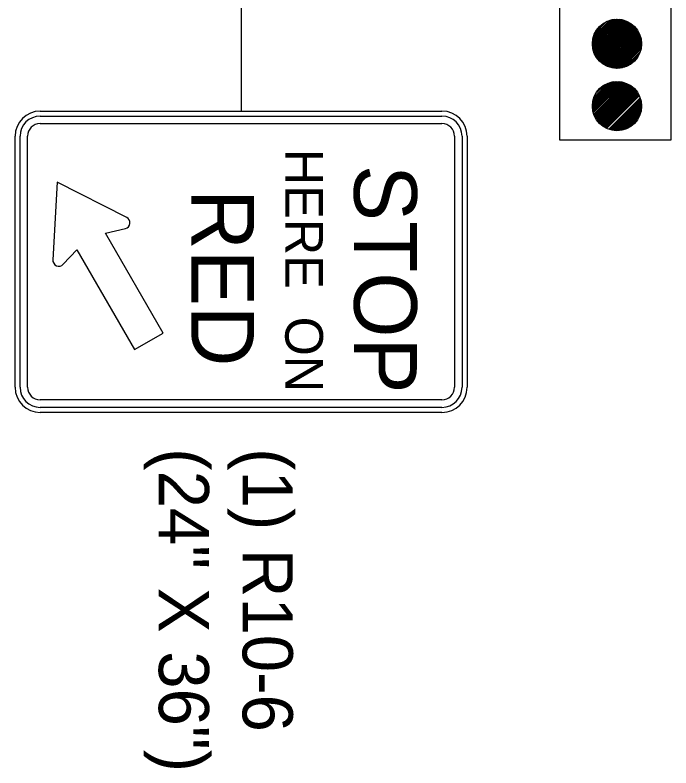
# Model space of a CAD drawing. Extents: x 1926586 to 1930787, y 596452 to 599566.
# Drawn here: x 1928552.1 to 1928630.5, y 597303.5 to 597393.4 of the extents above; entities that cross this region are included whole.
import ezdxf

# ---------------------------------------------------------------- set-up
doc = ezdxf.new("R2010")
doc.units = 0
for name, color, linetype in [('Default', 7, 'Continuous'), ('P_TC_Signs_Permanent', 7, 'Continuous'), ('R_Border', 7, 'Continuous')]:
    doc.layers.add(name, color=color, linetype=linetype)

msp = doc.modelspace()

# ---------------------------------------------------------------- linework, layer by layer
at = {"layer": 'Default'}
for p, q in [((1928621.108, 597390.048), (1928624.007, 597392.947)), ((1928621.111, 597389.87), (1928624.185, 597392.944)), ((1928621.117, 597390.238), (1928623.817, 597392.938)), ((1928621.124, 597389.702), (1928624.353, 597392.932)), ((1928621.14, 597390.442), (1928623.613, 597392.915)), ((1928621.145, 597389.542), (1928624.513, 597392.911)), ((1928621.173, 597389.389), (1928624.666, 597392.882)), ((1928621.183, 597390.665), (1928623.39, 597392.872)), ((1928621.208, 597389.244), (1928624.811, 597392.847)), ((1928621.249, 597389.104), (1928624.951, 597392.806)), ((1928621.252, 597390.916), (1928623.14, 597392.803)), ((1928621.296, 597388.97), (1928625.085, 597392.759)), ((1928621.348, 597388.841), (1928625.214, 597392.707)), ((1928621.366, 597391.21), (1928622.845, 597392.689)), ((1928621.405, 597388.717), (1928625.338, 597392.65)), ((1928621.467, 597388.598), (1928625.457, 597392.588)), ((1928621.533, 597388.483), (1928625.572, 597392.522)), ((1928621.582, 597391.608), (1928622.448, 597392.473)), ((1928621.603, 597388.372), (1928625.683, 597392.452)), ((1928621.677, 597388.266), (1928625.789, 597392.378)), ((1928621.756, 597388.164), (1928625.892, 597392.299)), ((1928621.839, 597388.065), (1928625.99, 597392.217)), ((1928621.925, 597387.971), (1928626.084, 597392.13)), ((1928622.016, 597387.88), (1928626.175, 597392.04)), ((1928622.11, 597387.794), (1928626.261, 597391.945)), ((1928622.208, 597387.711), (1928626.344, 597391.847)), ((1928622.311, 597387.633), (1928626.422, 597391.744)), ((1928622.417, 597387.558), (1928626.497, 597391.638)), ((1928622.528, 597387.488), (1928626.567, 597391.527)), ((1928622.643, 597387.422), (1928626.633, 597391.412)), ((1928622.762, 597387.361), (1928626.695, 597391.293)), ((1928622.886, 597387.304), (1928626.751, 597391.169)), ((1928623.015, 597387.252), (1928626.803, 597391.04)), ((1928623.149, 597387.205), (1928626.85, 597390.906)), ((1928623.289, 597387.164), (1928626.891, 597390.766)), ((1928623.435, 597387.129), (1928626.926, 597390.62)), ((1928623.587, 597387.1), (1928626.955, 597390.468)), ((1928623.747, 597387.079), (1928626.976, 597390.308)), ((1928623.916, 597387.067), (1928626.988, 597390.14)), ((1928624.094, 597387.064), (1928626.991, 597389.962)), ((1928624.284, 597387.073), (1928626.982, 597389.772)), ((1928624.488, 597387.097), (1928626.958, 597389.567)), ((1928624.711, 597387.139), (1928626.916, 597389.344)), ((1928624.962, 597387.209), (1928626.846, 597389.093)), ((1928625.257, 597387.323), (1928626.732, 597388.798)), ((1928625.656, 597387.541), (1928626.514, 597388.399)), ((1928621.108, 597382.529), (1928624.087, 597385.508)), ((1928621.112, 597382.713), (1928623.903, 597385.505)), ((1928621.115, 597382.355), (1928624.261, 597385.501)), ((1928621.128, 597382.911), (1928623.706, 597385.488)), ((1928621.132, 597382.191), (1928624.425, 597385.484)), ((1928621.156, 597382.034), (1928624.582, 597385.46)), ((1928621.161, 597383.125), (1928623.491, 597385.455)), ((1928621.188, 597381.885), (1928624.731, 597385.428)), ((1928621.217, 597383.362), (1928623.254, 597385.399)), ((1928621.226, 597381.742), (1928624.874, 597385.39)), ((1928621.27, 597381.605), (1928625.011, 597385.347)), ((1928621.308, 597383.633), (1928622.983, 597385.308)), ((1928621.319, 597381.473), (1928625.143, 597385.297)), ((1928621.373, 597381.346), (1928625.27, 597385.243)), ((1928621.432, 597381.225), (1928625.392, 597385.184)), ((1928621.465, 597383.971), (1928622.645, 597385.151)), ((1928621.495, 597381.107), (1928625.509, 597385.121)), ((1928621.563, 597380.994), (1928625.622, 597385.053)), ((1928621.635, 597380.886), (1928625.731, 597384.981)), ((1928621.712, 597380.781), (1928625.835, 597384.904)), ((1928621.792, 597380.68), (1928625.936, 597384.824)), ((1928621.876, 597380.584), (1928626.032, 597384.74)), ((1928621.965, 597380.491), (1928626.125, 597384.651)), ((1928622.057, 597380.403), (1928626.214, 597384.559)), ((1928622.153, 597380.318), (1928626.298, 597384.463)), ((1928622.253, 597380.237), (1928626.379, 597384.363)), ((1928622.357, 597380.16), (1928626.456, 597384.259)), ((1928622.466, 597380.088), (1928626.528, 597384.15)), ((1928622.578, 597380.019), (1928626.597, 597384.038)), ((1928622.695, 597379.955), (1928626.661, 597383.921)), ((1928622.816, 597379.896), (1928626.72, 597383.8)), ((1928623.074, 597379.791), (1928626.825, 597383.542)), ((1928623.21, 597379.747), (1928626.869, 597383.406)), ((1928623.353, 597379.709), (1928626.908, 597383.263)), ((1928623.501, 597379.676), (1928626.94, 597383.115)), ((1928623.657, 597379.651), (1928626.965, 597382.959)), ((1928623.821, 597379.634), (1928626.982, 597382.796)), ((1928623.993, 597379.625), (1928626.991, 597382.623)), ((1928624.176, 597379.628), (1928626.989, 597382.44)), ((1928624.372, 597379.643), (1928626.974, 597382.244)), ((1928624.584, 597379.674), (1928626.942, 597382.032)), ((1928624.818, 597379.727), (1928626.889, 597381.798)), ((1928625.085, 597379.813), (1928626.803, 597381.531)), ((1928625.413, 597379.96), (1928626.656, 597381.203)), ((1928625.986, 597380.352), (1928626.264, 597380.63))]:
    msp.add_line(p, q, dxfattribs=at)
msp.add_lwpolyline([(1928617.205, 597403.018), (1928630.498, 597403.018), (1928630.498, 597378.483), (1928617.205, 597378.483)], close=True, dxfattribs=at)
for centre in [(1928624.05, 597390.006), (1928624.05, 597382.567)]:
    msp.add_circle(centre, 2.942, dxfattribs=at)
at = {"layer": 'P_TC_Signs_Permanent'}
for p, q in [((1928555.145, 597381.967), (1928603.145, 597381.967)), ((1928555.145, 597381.367), (1928603.145, 597381.367)), ((1928555.145, 597380.467), (1928603.145, 597380.467)), ((1928552.145, 597348.967), (1928552.145, 597378.967)), ((1928552.745, 597348.967), (1928552.745, 597378.967)), ((1928553.645, 597348.967), (1928553.645, 597378.967)), ((1928604.645, 597378.967), (1928604.645, 597348.967)), ((1928605.545, 597378.967), (1928605.545, 597348.967)), ((1928606.145, 597378.967), (1928606.145, 597348.967)), ((1928603.145, 597347.467), (1928555.145, 597347.467)), ((1928603.145, 597346.567), (1928555.145, 597346.567)), ((1928603.145, 597345.967), (1928555.145, 597345.967))]:
    msp.add_line(p, q, dxfattribs=at)
for points in [[(1928565.482, 597369.268), (1928557.16, 597373.466), (1928556.651, 597364.196)], [(1928557.894, 597363.662), (1928559.54, 597365.406), (1928566.424, 597353.483), (1928569.834, 597355.452), (1928562.95, 597367.375), (1928565.32, 597367.923)]]:
    msp.add_lwpolyline(points, dxfattribs=at)
for centre, radius, start, end in [((1928555.145, 597378.967), 3, 90, 180), ((1928555.145, 597378.967), 2.4, 90, 180), ((1928603.145, 597378.967), 3, 360, 90), ((1928603.145, 597378.967), 2.4, 360, 90), ((1928555.145, 597378.967), 1.5, 90, 180), ((1928603.145, 597378.967), 1.5, 360, 90), ((1928565.158, 597368.625), 0.72, 283.03493, 63.22861), ((1928557.37, 597364.157), 0.72, 176.85697, 316.6377), ((1928555.145, 597348.967), 3, 180, 270), ((1928555.145, 597348.967), 2.4, 180, 270), ((1928555.145, 597348.967), 1.5, 180, 270), ((1928603.145, 597348.967), 3, 270, 360), ((1928603.145, 597348.967), 2.4, 270, 360), ((1928603.145, 597348.967), 1.5, 270, 360)]:
    msp.add_arc(centre, radius, start, end, dxfattribs=at)
at = {"layer": 'R_Border'}
msp.add_line((1928579.145, 597398.994), (1928579.145, 597381.967), dxfattribs=at)

# ---------------------------------------------------------------- texts
at = {"layer": 'P_TC_Signs_Permanent'}
for s, height, p in [('HERE  ON', 4.5, (1928584.425, 597377.467)), ('STOP', 7.5, (1928592.645, 597375.53)), ('RED', 7.5, (1928573.205, 597372.637))]:
    msp.add_text(s, height=height, rotation=270, dxfattribs=at).set_placement(p)
at = {"layer": 'R_Border'}
for s, height, p in [('(24" X 36")', 5.99957, (1928569.317, 597341.69)), ('(1) R10-6', 5.9996, (1928579.324, 597341.69))]:
    msp.add_text(s, height=height, rotation=270, dxfattribs=at).set_placement(p)

doc.saveas('drawing.dxf')
